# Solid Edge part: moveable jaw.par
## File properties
Title: Moveable Jaw
Author: Robert a Rhodes jr
Template: Normal.par
Last saved by: Cadcim
Revision: 12
Application: Solid Edge
Material: iron
Accuracy: 0.99
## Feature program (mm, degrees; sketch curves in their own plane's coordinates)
sketch for "unnamed Protrusion 1" plane through (0, 0, 0) normal (0, -1, 0) x-axis (1, 0, 0)
  line (-36.5256, 25.2528) -> (-36.5256, -34.7472)
  line (-36.5256, -34.7472) -> (-33.0256, -34.7472)
  line (-33.0256, -34.7472) -> (-33.0256, -32.2472)
  line (-33.0256, -32.2472) -> (-30.5256, -32.2472)
  line (-30.5256, -32.2472) -> (-30.5256, -29.7472)
  line (-30.5256, -29.7472) -> (-28.0256, -29.7472)
  line (-28.0256, -29.7472) -> (-28.0256, -27.2472)
  line (-28.0256, -27.2472) -> (-25.5256, -27.2472)
  line (-25.5256, -27.2472) -> (-25.5256, -24.7472)
  line (-25.5256, -24.7472) -> (-23.0256, -24.7472)
  line (-23.0256, -24.7472) -> (-23.0256, -22.2472)
  line (-23.0256, -22.2472) -> (-20.5256, -22.2472)
  line (-20.5256, -22.2472) -> (-20.5256, -19.7472)
  line (-20.5256, -19.7472) -> (-18.0256, -19.7472)
  line (-18.0256, -22.2472) -> (-18.0256, -19.7472)
  line (-15.5256, -22.2472) -> (-18.0256, -22.2472)
  line (-15.5256, -24.7472) -> (-15.5256, -22.2472)
  line (-13.0256, -24.7472) -> (-15.5256, -24.7472)
  line (-13.0256, -27.2472) -> (-13.0256, -24.7472)
  line (-10.5256, -27.2472) -> (-13.0256, -27.2472)
  line (-10.5256, -29.7472) -> (-10.5256, -27.2472)
  line (-8.0256, -29.7472) -> (-10.5256, -29.7472)
  line (-8.0256, -32.2472) -> (-8.0256, -29.7472)
  line (-5.5256, -32.2472) -> (-8.0256, -32.2472)
  line (-5.5256, -34.7472) -> (-5.5256, -32.2472)
  line (-2.0256, -34.7472) -> (-5.5256, -34.7472)
  line (-2.0256, -34.7472) -> (-2.0256, 25.2528)
  line (-2.0256, 25.2528) -> (-36.5256, 25.2528)
extrude "unnamed Protrusion 1" add finite 18 along -normal
sketch for "Hole_1" plane through (-19.2756, 9, 25.2528) normal (0, 0, 1) x-axis (1, 0, 0)
  hole centre (0, 0) bore radius 6
hole "Hole_1" diameter 12 finite  VBottomAngle = 118 deg
sketch for "Hole_2" plane through (-2.0256, 9, -4.7472) normal (1, 0, 0) x-axis (0, 1, 0)
  hole centre (0, 23) bore radius 4.5
hole "Hole_2" diameter 9 through
chamfer "Chamfer_1" setback 2
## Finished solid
Body 1: solid body, 38 faces, 98 edges, 60 vertices.
  Faces by surface: plane 34, cylinder 3, cone 1
  Edges by curve: line 92, circle 4, intersection 2
Bounding box of the edges (mm): 34.500 x 18.000 x 60.000, from (-36.5256, 0, -34.7472) to (-2.0256, 18, 25.2528).
Cylindrical faces by radius (mm): R4.5 x2, R6 x1
Conical faces (half-angle, radius in mm at the cone's reference point): 59 deg R6 x1
Planar faces by outward normal: +x 7, +y 1, +z 1, -x 7, -y 1, -z 13, oblique 4
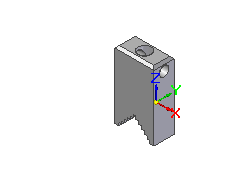
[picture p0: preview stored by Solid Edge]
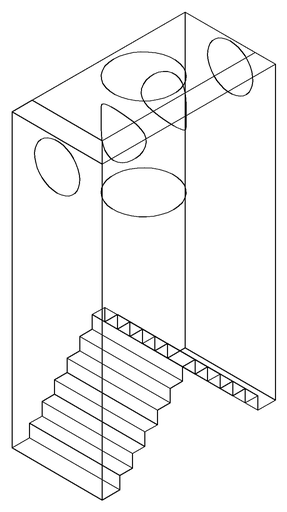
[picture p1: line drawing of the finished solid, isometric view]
